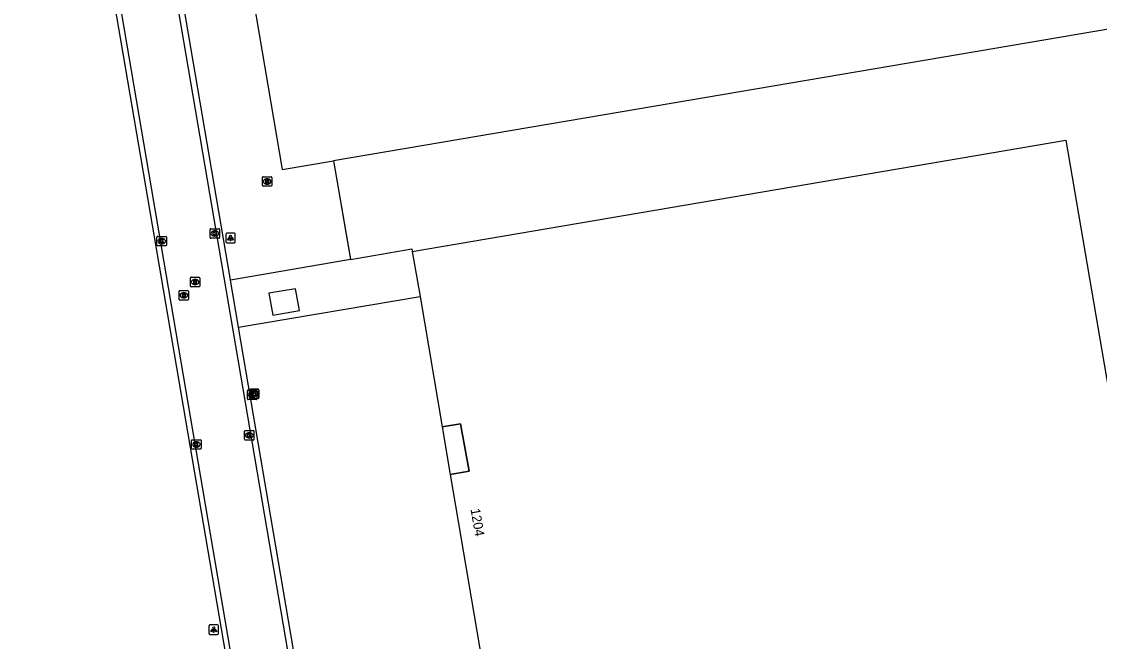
# Model space of a CAD drawing. Extents: x 154324 to 155743, y 382939 to 384183.
# Drawn here: x 154706.1 to 154819.6, y 383447.8 to 383513.1 of the extents above; entities that cross this region are included whole.
import ezdxf

# ---------------------------------------------------------------- set-up
doc = ezdxf.new("R2010")
doc.units = 0
for name, color, linetype in [('IMGEO_Brandkraan', 7, 'Continuous'), ('IMGEO_Hek', 7, 'Continuous'), ('IMGEO_Kolk', 7, 'Continuous'), ('IMGEO_Lage_trafo', 7, 'Continuous'), ('IMGEO_Lichtpunt', 7, 'Continuous'), ('IMGEO_Pand', 7, 'Continuous'), ('IMGEO_Pand_nummerreeks', 7, 'Continuous'), ('IMGEO_Pand_overbouw', 7, 'Continuous'), ('IMGEO_Rijbaan_lokaal_gesloten', 7, 'Continuous'), ('IMGEO_Rijbaan_lokaal_open', 7, 'Continuous'), ('IMGEO_Rioolput', 7, 'Continuous'), ('IMGEO_Terreindeel_open', 7, 'Continuous'), ('IMGEO_Verklikker', 7, 'Continuous'), ('IMGEO_Voetpad_open', 7, 'Continuous')]:
    doc.layers.add(name, color=color, linetype=linetype)

msp = doc.modelspace()

# ---------------------------------------------------------------- linework, layer by layer
at = {"layer": 'IMGEO_Brandkraan'}
for p, q in [((154729.88, 383473.37), (154729.88, 383474.22)), ((154729.95, 383474.29), (154730.8, 383474.29)), ((154730.88, 383474.22), (154730.88, 383473.37)), ((154730.8, 383473.29), (154729.95, 383473.29)), ((154730.36, 383474.07), (154730.39, 383474.07)), ((154730.39, 383473.51), (154730.36, 383473.51))]:
    msp.add_line(p, q, dxfattribs=at)
for points in [[(154729.88, 383473.37), (154729.88, 383474.22)], [(154729.95, 383474.29), (154730.8, 383474.29)], [(154730.88, 383474.22), (154730.88, 383473.37)], [(154730.8, 383473.29), (154729.95, 383473.29)], [(154730.22, 383473.99), (154730.22, 383473.59), (154730.44, 383473.59)], [(154730.46, 383473.99), (154730.22, 383473.99)], [(154730.4, 383473.91), (154730.35, 383473.91), (154730.35, 383473.84)], [(154730.35, 383473.84), (154730.4, 383473.84)], [(154730.41, 383473.76), (154730.35, 383473.76), (154730.35, 383473.68)], [(154730.35, 383473.68), (154730.41, 383473.68)]]:
    msp.add_lwpolyline(points, dxfattribs=at)
for centre, radius, start, end in [((154729.95, 383474.22), 0.0765, 91.552, 178.448), ((154729.95, 383474.22), 0.0765, 91.552, 178.448), ((154730.8, 383474.22), 0.0765, 1.552, 88.448), ((154730.8, 383474.22), 0.0765, 1.552, 88.448), ((154729.95, 383473.37), 0.0765, 181.552, 268.448), ((154729.95, 383473.37), 0.0765, 181.552, 268.448), ((154730.4, 383473.87), 0.0379, 267.8285, 90.9355), ((154730.41, 383473.72), 0.0404, 269.8759, 90.5077), ((154730.44, 383473.84), 0.251, 268.6676, 293.5347), ((154730.46, 383473.85), 0.145, 59.4692, 91.5367), ((154730.48, 383473.89), 0.0922, 285.5137, 58.1501), ((154730.49, 383473.7), 0.105, 301.3115, 78.989), ((154730.8, 383473.37), 0.0765, 271.552, 358.448), ((154730.8, 383473.37), 0.0765, 271.552, 358.448)]:
    msp.add_arc(centre, radius, start, end, dxfattribs=at)
for centre, major_axis, ratio, start_param, end_param in [((154730.36, 383473.79), (-0.387, 0.002), 0.722429, 4.712389, 7.853982), ((154730.39, 383473.79), (-0.39, 0.002), 0.717154, 1.570796, 4.712389)]:
    msp.add_ellipse(centre, major_axis=major_axis, ratio=ratio, start_param=start_param, end_param=end_param, dxfattribs=at)
at = {"layer": 'IMGEO_Hek'}
msp.add_lwpolyline([(154738.94, 383498.45), (154740.73, 383488.07)], dxfattribs=at)
at = {"layer": 'IMGEO_Kolk'}
for p, q in [((154725.95, 383490.37), (154725.95, 383491.23)), ((154726.02, 383491.3), (154726.87, 383491.3)), ((154726.95, 383491.23), (154726.95, 383490.37)), ((154720.35, 383489.57), (154720.35, 383490.42)), ((154720.42, 383490.49), (154721.28, 383490.49)), ((154720.84, 383490.27), (154720.86, 383490.27)), ((154721.35, 383490.42), (154721.35, 383489.57)), ((154726.87, 383490.3), (154726.02, 383490.3)), ((154726.43, 383491.08), (154726.46, 383491.08)), ((154726.46, 383490.52), (154726.43, 383490.52)), ((154721.28, 383489.49), (154720.42, 383489.49)), ((154720.86, 383489.71), (154720.83, 383489.71)), ((154729.57, 383469.11), (154729.57, 383469.96)), ((154729.65, 383470.03), (154730.5, 383470.03)), ((154730.06, 383469.81), (154730.09, 383469.81)), ((154730.57, 383469.96), (154730.57, 383469.11)), ((154724, 383468.14), (154724, 383469)), ((154724.07, 383469.07), (154724.93, 383469.07)), ((154724.49, 383468.85), (154724.51, 383468.85)), ((154725, 383469), (154725, 383468.14)), ((154730.5, 383469.03), (154729.65, 383469.03)), ((154730.08, 383469.25), (154730.06, 383469.25)), ((154724.93, 383468.07), (154724.07, 383468.07)), ((154724.51, 383468.29), (154724.48, 383468.29))]:
    msp.add_line(p, q, dxfattribs=at)
for points in [[(154725.95, 383490.37), (154725.95, 383491.23)], [(154726.02, 383491.3), (154726.87, 383491.3)], [(154726.95, 383491.23), (154726.95, 383490.37)], [(154720.35, 383489.57), (154720.35, 383490.42)], [(154720.42, 383490.49), (154721.28, 383490.49)], [(154720.67, 383490.19), (154720.79, 383490.19), (154720.79, 383490.04), (154720.92, 383490.19), (154721.09, 383490.19), (154720.94, 383490.04), (154721.09, 383489.79), (154720.94, 383489.79), (154720.86, 383489.96), (154720.79, 383489.89), (154720.79, 383489.79), (154720.67, 383489.79), (154720.67, 383490.19)], [(154721.35, 383490.42), (154721.35, 383489.57)], [(154726.87, 383490.3), (154726.02, 383490.3)], [(154726.27, 383491), (154726.39, 383491), (154726.39, 383490.85), (154726.52, 383491), (154726.68, 383491), (154726.54, 383490.85), (154726.69, 383490.6), (154726.54, 383490.6), (154726.45, 383490.76), (154726.39, 383490.7), (154726.39, 383490.6), (154726.27, 383490.6), (154726.27, 383491)], [(154721.28, 383489.49), (154720.42, 383489.49)], [(154729.57, 383469.11), (154729.57, 383469.96)], [(154729.65, 383470.03), (154730.5, 383470.03)], [(154729.89, 383469.73), (154730.02, 383469.73), (154730.02, 383469.58), (154730.15, 383469.73), (154730.31, 383469.73), (154730.16, 383469.58), (154730.32, 383469.33), (154730.16, 383469.33), (154730.08, 383469.5), (154730.02, 383469.43), (154730.02, 383469.33), (154729.89, 383469.33), (154729.89, 383469.73)], [(154730.57, 383469.96), (154730.57, 383469.11)], [(154724, 383468.14), (154724, 383469)], [(154724.07, 383469.07), (154724.93, 383469.07)], [(154724.32, 383468.77), (154724.44, 383468.77), (154724.44, 383468.62), (154724.57, 383468.77), (154724.74, 383468.77), (154724.59, 383468.62), (154724.74, 383468.37), (154724.59, 383468.37), (154724.51, 383468.54), (154724.44, 383468.47), (154724.44, 383468.37), (154724.32, 383468.37), (154724.32, 383468.77)], [(154725, 383469), (154725, 383468.14)], [(154730.5, 383469.03), (154729.65, 383469.03)], [(154724.93, 383468.07), (154724.07, 383468.07)]]:
    msp.add_lwpolyline(points, dxfattribs=at)
for centre, start, end in [((154726.02, 383491.22), 91.552, 178.448), ((154726.02, 383491.22), 91.552, 178.448), ((154726.87, 383491.22), 1.552, 88.448), ((154726.87, 383491.22), 1.552, 88.448), ((154720.43, 383490.42), 91.552, 178.448), ((154720.43, 383490.42), 91.552, 178.448), ((154721.27, 383490.42), 1.552, 88.448), ((154721.27, 383490.42), 1.552, 88.448), ((154726.02, 383490.37), 181.552, 268.448), ((154726.02, 383490.37), 181.552, 268.448), ((154726.87, 383490.37), 271.552, 358.448), ((154726.87, 383490.37), 271.552, 358.448), ((154720.43, 383489.57), 181.552, 268.448), ((154720.43, 383489.57), 181.552, 268.448), ((154721.27, 383489.57), 271.552, 358.448), ((154721.27, 383489.57), 271.552, 358.448), ((154729.65, 383469.96), 91.552, 178.448), ((154729.65, 383469.96), 91.552, 178.448), ((154730.5, 383469.96), 1.552, 88.448), ((154730.5, 383469.96), 1.552, 88.448), ((154724.07, 383469), 91.552, 178.448), ((154724.07, 383469), 91.552, 178.448), ((154724.92, 383469), 1.552, 88.448), ((154724.92, 383469), 1.552, 88.448), ((154729.65, 383469.11), 181.552, 268.448), ((154729.65, 383469.11), 181.552, 268.448), ((154730.5, 383469.11), 271.552, 358.448), ((154730.5, 383469.11), 271.552, 358.448), ((154724.07, 383468.15), 181.552, 268.448), ((154724.07, 383468.15), 181.552, 268.448), ((154724.92, 383468.15), 271.552, 358.448), ((154724.92, 383468.15), 271.552, 358.448)]:
    msp.add_arc(centre, 0.0765, start, end, dxfattribs=at)
for centre, major_axis, ratio, start_param, end_param in [((154720.84, 383489.99), (-0.387, 0.002), 0.722429, 4.712389, 7.853982), ((154720.86, 383489.99), (-0.39, 0.002), 0.717154, 1.570796, 4.712389), ((154726.43, 383490.8), (-0.387, 0.002), 0.722429, 4.712389, 7.853982), ((154726.46, 383490.8), (-0.39, 0.002), 0.717154, 1.570796, 4.712389), ((154730.06, 383469.53), (-0.387, 0.002), 0.722429, 4.712389, 7.853982), ((154730.08, 383469.53), (-0.39, 0.002), 0.717154, 1.570796, 4.712389), ((154724.49, 383468.57), (-0.387, 0.002), 0.722429, 4.712389, 7.853982), ((154724.51, 383468.57), (-0.39, 0.002), 0.717154, 1.570796, 4.712389)]:
    msp.add_ellipse(centre, major_axis=major_axis, ratio=ratio, start_param=start_param, end_param=end_param, dxfattribs=at)
at = {"layer": 'IMGEO_Lage_trafo'}
msp.add_lwpolyline([(154734.96, 383484.97), (154732.15, 383484.49), (154732.55, 383482.19), (154735.36, 383482.68), (154734.96, 383484.97)], dxfattribs=at)
at = {"layer": 'IMGEO_Lichtpunt'}
for p, q in [((154727.61, 383490.73), (154727.61, 383489.92)), ((154727.61, 383490.73), (154727.61, 383489.92)), ((154728.51, 383490.82), (154727.7, 383490.82)), ((154728.51, 383490.82), (154727.7, 383490.82)), ((154728.6, 383489.92), (154728.6, 383490.73)), ((154728.6, 383489.92), (154728.6, 383490.73)), ((154727.7, 383489.82), (154728.51, 383489.82)), ((154727.7, 383489.82), (154728.51, 383489.82)), ((154725.83, 383449.46), (154725.83, 383448.65)), ((154725.83, 383449.46), (154725.83, 383448.65)), ((154726.74, 383449.55), (154725.93, 383449.55)), ((154726.74, 383449.55), (154725.93, 383449.55)), ((154726.83, 383448.65), (154726.83, 383449.46)), ((154726.83, 383448.65), (154726.83, 383449.46)), ((154725.93, 383448.55), (154726.74, 383448.55)), ((154725.93, 383448.55), (154726.74, 383448.55))]:
    msp.add_line(p, q, dxfattribs=at)
for points in [[(154727.98, 383490.39), (154728.02, 383490.36), (154727.83, 383490.1), (154727.79, 383490.13), (154727.98, 383490.39)], [(154728.08, 383490.34), (154728.13, 383490.34), (154728.13, 383490.02), (154728.08, 383490.02), (154728.08, 383490.34)], [(154728.19, 383490.36), (154728.23, 383490.39), (154728.42, 383490.13), (154728.38, 383490.1), (154728.19, 383490.36)], [(154726.21, 383449.12), (154726.25, 383449.09), (154726.06, 383448.83), (154726.02, 383448.86), (154726.21, 383449.12)], [(154726.31, 383449.07), (154726.36, 383449.07), (154726.36, 383448.75), (154726.31, 383448.75), (154726.31, 383449.07)], [(154726.42, 383449.09), (154726.46, 383449.12), (154726.65, 383448.86), (154726.61, 383448.83), (154726.42, 383449.09)]]:
    msp.add_lwpolyline(points, dxfattribs=at)
for centre in [(154728.11, 383490.52), (154726.33, 383449.25)]:
    msp.add_circle(centre, 0.0994, dxfattribs=at)
for centre, start, end in [((154727.7, 383490.73), 90, 180), ((154727.7, 383490.73), 90, 180), ((154728.51, 383490.73), 0, 90), ((154728.51, 383490.73), 0, 90), ((154727.7, 383489.92), 180, 270), ((154727.7, 383489.92), 180, 270), ((154728.51, 383489.92), 270, 0), ((154728.51, 383489.92), 270, 360), ((154725.93, 383449.46), 90, 180), ((154725.93, 383449.46), 90, 180), ((154726.74, 383449.46), 0, 90), ((154726.74, 383449.46), 0, 90), ((154725.93, 383448.65), 180, 270), ((154725.93, 383448.65), 180, 270), ((154726.74, 383448.65), 270, 0), ((154726.74, 383448.65), 270, 360)]:
    msp.add_arc(centre, 0.0946, start, end, dxfattribs=at)
at = {"layer": 'IMGEO_Pand'}
for points in [[(154879.18, 383621.22), (154895.56, 383525.11), (154815.63, 383511.49), (154769.14, 383503.59), (154738.94, 383498.45)], [(154717.25, 383593.65), (154717.21, 383593.64), (154733.53, 383497.52), (154738.94, 383498.45)], [(154747.25, 383488.9), (154816.1, 383500.63), (154832.97, 383401.91), (154774.29, 383391.51), (154774.27, 383391.62)], [(154747.25, 383488.9), (154748.06, 383484.15)], [(154748.06, 383484.15), (154750.39, 383470.42), (154752.32, 383470.75), (154753.23, 383465.74), (154751.24, 383465.4), (154754.6, 383445.61)]]:
    msp.add_lwpolyline(points, dxfattribs=at)
at = {"layer": 'IMGEO_Pand_overbouw'}
msp.add_lwpolyline([(154750.39, 383470.42), (154751.24, 383465.4), (154753.23, 383465.74), (154752.32, 383470.75)], close=True, dxfattribs=at)
at = {"layer": 'IMGEO_Rijbaan_lokaal_gesloten'}
for points in [[(154789.63, 383121.11), (154789.03, 383124.4), (154786.39, 383140.02), (154764.04, 383271.32), (154739.67, 383414.35), (154710.41, 383586), (154685.55, 383732.21), (154684.2, 383740.13)], [(154785.66, 383108.36), (154783.65, 383120.27), (154783.5, 383121.23), (154748.65, 383326.31), (154679.93, 383729.19), (154679.26, 383733.15)], [(154695.76, 383632.98), (154705.98, 383572.84), (154731.57, 383423.07), (154733.05, 383414.37), (154733.72, 383410.4), (154735.43, 383400.34), (154736.07, 383396.59)]]:
    msp.add_lwpolyline(points, dxfattribs=at)
at = {"layer": 'IMGEO_Rijbaan_lokaal_open'}
for points in [[(154728.09, 383485.86), (154728.09, 383485.9), (154713.13, 383573.57), (154707.82, 383604.93)], [(154728.93, 383480.92), (154728.09, 383485.86)], [(154753.52, 383336.76), (154752.34, 383343.73), (154728.93, 383480.92)]]:
    msp.add_lwpolyline(points, dxfattribs=at)
at = {"layer": 'IMGEO_Rioolput'}
for p, q in [((154731.46, 383495.85), (154731.46, 383496.7)), ((154731.53, 383496.77), (154732.39, 383496.77)), ((154732.39, 383495.77), (154731.53, 383495.77)), ((154731.97, 383495.99), (154731.94, 383495.99)), ((154731.95, 383496.55), (154731.97, 383496.55)), ((154732.46, 383496.7), (154732.46, 383495.85)), ((154723.87, 383485.25), (154723.87, 383486.11)), ((154723.94, 383486.18), (154724.8, 383486.18)), ((154724.36, 383485.96), (154724.38, 383485.96)), ((154724.87, 383486.11), (154724.87, 383485.25)), ((154722.68, 383483.85), (154722.68, 383484.7)), ((154722.75, 383484.78), (154723.61, 383484.78)), ((154723.17, 383484.56), (154723.19, 383484.56)), ((154723.68, 383484.7), (154723.68, 383483.85)), ((154724.8, 383485.18), (154723.94, 383485.18)), ((154724.38, 383485.4), (154724.35, 383485.4)), ((154723.61, 383483.78), (154722.75, 383483.78)), ((154723.19, 383484), (154723.17, 383484))]:
    msp.add_line(p, q, dxfattribs=at)
for points in [[(154731.46, 383495.85), (154731.46, 383496.7)], [(154731.53, 383496.77), (154732.39, 383496.77)], [(154732.39, 383495.77), (154731.53, 383495.77)], [(154732.05, 383496.47), (154731.8, 383496.47), (154731.8, 383496.07)], [(154731.8, 383496.07), (154731.92, 383496.07), (154731.92, 383496.23), (154731.93, 383496.23)], [(154731.97, 383496.39), (154731.92, 383496.39), (154731.92, 383496.31)], [(154731.92, 383496.31), (154731.97, 383496.31)], [(154731.98, 383496.2), (154732.05, 383496.07), (154732.19, 383496.07), (154732.12, 383496.2)], [(154732.46, 383496.7), (154732.46, 383495.85)], [(154723.87, 383485.25), (154723.87, 383486.11)], [(154723.94, 383486.18), (154724.8, 383486.18)], [(154724.46, 383485.88), (154724.21, 383485.88), (154724.21, 383485.48)], [(154724.21, 383485.48), (154724.33, 383485.48), (154724.33, 383485.64), (154724.34, 383485.64)], [(154724.38, 383485.8), (154724.33, 383485.8), (154724.33, 383485.72)], [(154724.33, 383485.72), (154724.38, 383485.72)], [(154724.39, 383485.61), (154724.46, 383485.48), (154724.6, 383485.48), (154724.53, 383485.61)], [(154724.87, 383486.11), (154724.87, 383485.25)], [(154722.68, 383483.85), (154722.68, 383484.7)], [(154722.75, 383484.78), (154723.61, 383484.78)], [(154723.27, 383484.48), (154723.02, 383484.48), (154723.02, 383484.08)], [(154723.2, 383484.4), (154723.14, 383484.4), (154723.14, 383484.32)], [(154723.68, 383484.7), (154723.68, 383483.85)], [(154724.8, 383485.18), (154723.94, 383485.18)], [(154723.61, 383483.78), (154722.75, 383483.78)], [(154723.02, 383484.08), (154723.14, 383484.08), (154723.14, 383484.24), (154723.15, 383484.24)], [(154723.14, 383484.32), (154723.19, 383484.32)], [(154723.2, 383484.21), (154723.27, 383484.08), (154723.41, 383484.08), (154723.34, 383484.2)]]:
    msp.add_lwpolyline(points, dxfattribs=at)
for centre, radius, start, end in [((154731.54, 383496.7), 0.0765, 91.552, 178.448), ((154731.54, 383496.7), 0.0765, 91.552, 178.448), ((154731.54, 383495.85), 0.0765, 181.552, 268.448), ((154731.54, 383495.85), 0.0765, 181.552, 268.448), ((154731.93, 383496.18), 0.0533, 26.0293, 88.6989), ((154731.98, 383496.29), 0.0964, 77.0061, 93.1865), ((154731.96, 383496.5), 0.19, 274.7715, 282.9687), ((154731.99, 383496.35), 0.0378, 276.6634, 79.6772), ((154732.05, 383496.36), 0.109, 350.3612, 89.416), ((154732.05, 383496.36), 0.112, 277.5842, 350.9817), ((154732.03, 383496.14), 0.108, 29.5134, 73.7905), ((154732.38, 383496.7), 0.0765, 1.552, 88.448), ((154732.38, 383496.7), 0.0765, 1.552, 88.448), ((154732.38, 383495.85), 0.0765, 271.552, 358.448), ((154732.38, 383495.85), 0.0765, 271.552, 358.448), ((154723.95, 383486.1), 0.0765, 91.552, 178.448), ((154723.95, 383486.1), 0.0765, 91.552, 178.448), ((154724.34, 383485.59), 0.0533, 26.0293, 88.6989), ((154724.39, 383485.7), 0.0964, 77.0061, 93.1865), ((154724.37, 383485.91), 0.19, 274.7715, 282.9687), ((154724.4, 383485.76), 0.0378, 276.6634, 79.6772), ((154724.46, 383485.77), 0.109, 350.3612, 89.416), ((154724.46, 383485.77), 0.112, 277.5842, 350.9817), ((154724.44, 383485.55), 0.108, 29.5134, 73.7905), ((154724.79, 383486.1), 0.0765, 1.552, 88.448), ((154724.79, 383486.1), 0.0765, 1.552, 88.448), ((154722.76, 383484.7), 0.0765, 91.552, 178.448), ((154722.76, 383484.7), 0.0765, 91.552, 178.448), ((154723.2, 383484.3), 0.0964, 77.0061, 93.1865), ((154723.22, 383484.36), 0.0378, 276.6634, 79.6772), ((154723.27, 383484.37), 0.109, 350.3612, 89.416), ((154723.27, 383484.37), 0.112, 277.5842, 350.9817), ((154723.6, 383484.7), 0.0765, 1.552, 88.448), ((154723.6, 383484.7), 0.0765, 1.552, 88.448), ((154723.95, 383485.26), 0.0765, 181.552, 268.448), ((154723.95, 383485.26), 0.0765, 181.552, 268.448), ((154724.79, 383485.26), 0.0765, 271.552, 358.448), ((154724.79, 383485.26), 0.0765, 271.552, 358.448), ((154722.76, 383483.85), 0.0765, 181.552, 268.448), ((154722.76, 383483.85), 0.0765, 181.552, 268.448), ((154723.15, 383484.19), 0.0533, 26.0293, 88.6989), ((154723.18, 383484.51), 0.19, 274.7715, 282.9687), ((154723.25, 383484.15), 0.108, 29.5134, 73.7905), ((154723.6, 383483.85), 0.0765, 271.552, 358.448), ((154723.6, 383483.85), 0.0765, 271.552, 358.448)]:
    msp.add_arc(centre, radius, start, end, dxfattribs=at)
for centre, major_axis, ratio, start_param, end_param in [((154731.95, 383496.27), (-0.387, 0.002), 0.722429, 4.712389, 7.853982), ((154731.97, 383496.27), (-0.39, 0.002), 0.717154, 1.570796, 4.712389), ((154724.36, 383485.68), (-0.387, 0.002), 0.722429, 4.712389, 7.853982), ((154724.38, 383485.68), (-0.39, 0.002), 0.717154, 1.570796, 4.712389), ((154723.17, 383484.28), (-0.387, 0.002), 0.722429, 4.712389, 7.853982), ((154723.19, 383484.28), (-0.39, 0.002), 0.717154, 1.570796, 4.712389)]:
    msp.add_ellipse(centre, major_axis=major_axis, ratio=ratio, start_param=start_param, end_param=end_param, dxfattribs=at)
at = {"layer": 'IMGEO_Terreindeel_open'}
msp.add_lwpolyline([(154738.94, 383498.45), (154740.73, 383488.05)], dxfattribs=at)
at = {"layer": 'IMGEO_Verklikker'}
for p, q in [((154730.11, 383473.5), (154730.11, 383474.3)), ((154730.11, 383474.3), (154730.11, 383473.5)), ((154730.21, 383474.4), (154731, 383474.4)), ((154731, 383474.4), (154730.21, 383474.4)), ((154731.1, 383474.3), (154731.1, 383473.5)), ((154731.1, 383473.5), (154731.1, 383474.3)), ((154731, 383473.4), (154730.21, 383473.4)), ((154730.21, 383473.4), (154731, 383473.4))]:
    msp.add_line(p, q, dxfattribs=at)
for points in [[(154730.21, 383474.13), (154731, 383474.13), (154731, 383473.67), (154730.21, 383473.67), (154730.21, 383474.13)], [(154730.27, 383474.07), (154730.27, 383473.73), (154730.93, 383473.73), (154730.93, 383474.07), (154730.27, 383474.07)]]:
    msp.add_lwpolyline(points, dxfattribs=at)
for centre, start, end in [((154730.21, 383474.3), 90, 180), ((154730.21, 383474.3), 90, 180), ((154731, 383474.3), 0, 90), ((154731, 383474.3), 360, 90), ((154730.21, 383473.5), 180, 270), ((154730.21, 383473.5), 180, 270), ((154731, 383473.5), 270, 0), ((154731, 383473.5), 270, 0)]:
    msp.add_arc(centre, 0.1, start, end, dxfattribs=at)
at = {"layer": 'IMGEO_Voetpad_open'}
for points in [[(154740.73, 383488.05), (154747.21, 383489.16), (154747.25, 383488.9)], [(154740.73, 383488.05), (154728.09, 383485.86)], [(154728.93, 383480.92), (154748.06, 383484.15)]]:
    msp.add_lwpolyline(points, dxfattribs=at)

# ---------------------------------------------------------------- texts
at = {"layer": 'IMGEO_Pand_nummerreeks'}
msp.add_text('1204', height=1, rotation=279.6369, dxfattribs=at).set_placement((154753.38, 383461.75))

doc.saveas('drawing.dxf')
